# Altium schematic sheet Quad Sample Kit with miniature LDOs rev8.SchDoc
size A
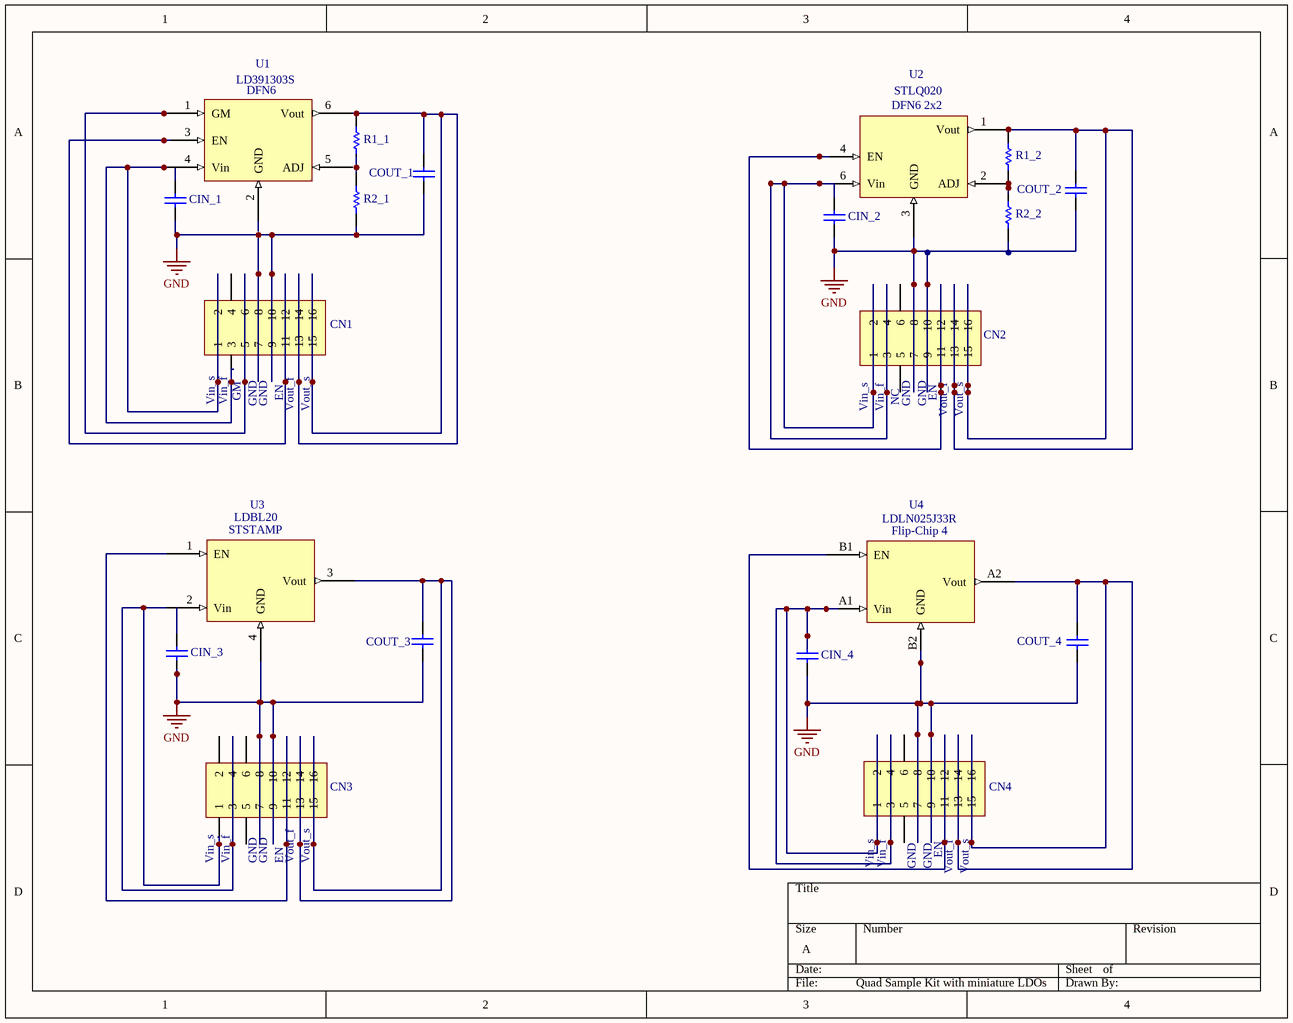
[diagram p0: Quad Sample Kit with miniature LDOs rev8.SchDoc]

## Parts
CIN_1  Cap  [0603]  (value not drawn)
CIN_2  Cap  [0603]  (value not drawn)
CIN_3  Cap  [0603]  (value not drawn)
CIN_4  Cap  [0603]  (value not drawn)
CN1  Header 8X2  [HDR2X8]  (value not drawn)
CN2  Header 8X2  [HDR2X8]  (value not drawn)
CN3  Header 8X2  [HDR2X8]  (value not drawn)
CN4  Header 8X2  [HDR2X8]  (value not drawn)
COUT_1  Cap  [0603]  (value not drawn)
COUT_2  Cap  [0603]  (value not drawn)
COUT_3  Cap  [0603]  (value not drawn)
COUT_4  Cap  [0603]  (value not drawn)
LD391303S  DFN6  [PCBComponent_1]
LDBL20  STSTAMP  [PCBComponent_1]
LDLN025J33R  Flip-Chip 4  [PCBComponent_1]
R1_1  Res1  [0603]  (value not drawn)
R1_2  Res1  [0603]  (value not drawn)
R2_1  Res1  [0603]  (value not drawn)
R2_2  Res1  [0603]  (value not drawn)
STLQ020  DFN6 2x2  [PCBComponent_1]

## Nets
GND: CIN_1.1 CIN_2.1 CIN_3.1 CIN_4.1 CN1.7 CN1.8 CN1.9 CN1.10 CN2.7 CN2.8 CN3.7 CN3.8 CN3.9 CN3.10 CN4.7 CN4.8 CN4.9 CN4.10 COUT_1.1 COUT_2.1 COUT_3.1 COUT_4.1 LDBL20.4(GND) LDLN025J33R.B2(GND) R2_1.1 STLQ020.3(GND)
NetCIN_2_2: CIN_2.2 CN2.1 CN2.2 CN2.3 CN2.4 STLQ020.6(Vin)
NetCIN_4_2: CIN_4.2 CN4.1 CN4.2 CN4.3 CN4.4 LDLN025J33R.A1(Vin)
NetCN1_1: CN1.1 CN1.2 CN1.3 LD391303S.4(Vin)
NetCN1_5: CN1.5 CN1.6 LD391303S.1(GM)
NetCN1_11: CN1.11 CN1.12 LD391303S.3(EN)
NetCN1_13: CN1.13 CN1.14 CN1.15 CN1.16 COUT_1.2 LD391303S.6(Vout) R1_1.2
NetCN2_9: CN2.9 CN2.10
NetCN2_11: CN2.11 CN2.12 STLQ020.4(EN)
NetCN2_13: CN2.13 CN2.14 CN2.15 CN2.16 COUT_2.2 R1_2.2 STLQ020.1(Vout)
NetCN3_1: CN3.1 CN3.3 CN3.4 LDBL20.2(Vin)
NetCN3_11: CN3.11 CN3.12 LDBL20.1(EN)
NetCN3_13: CN3.13 CN3.14 CN3.15 CN3.16 COUT_3.2 LDBL20.3(Vout)
NetCN4_11: CN4.11 CN4.12 LDLN025J33R.B1(EN)
NetCN4_13: CN4.13 CN4.14 CN4.15 CN4.16 COUT_4.2 LDLN025J33R.A2(Vout)
NetR1_1_1: R1_1.1 R2_1.2
NetR1_2_1: R1_2.1 R2_2.2 STLQ020.2(ADJ)

Not connected (* = marked no-connect by the designer): CIN_1 2; CIN_3 2; CN1 4; CN2 5 6; CN3 2 5 6; CN4 5 6; LD391303S 2(GND) 5(ADJ); R2_2 1

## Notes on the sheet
- (near LD391303S) U1
- (near STLQ020) U2
- (near CN1) Vin_s
- (near CN1) Vin_f
- (near CN1) GM
- (near CN1) GND
- (near CN1) EN
- (near CN1) Vout_f
- (near CN1) Vout_s
- (near CN2) Vin_s
- (near CN2) Vin_f
- (near CN2) NC
- (near CN2) GND
- (near CN2) EN
- (near CN2) Vout_f
- (near CN2) Vout_s
- (near LDBL20) U3
- (near LDLN025J33R) Flip-Chip 4
- (near LDLN025J33R) U4
- (near CN3) Vin_s
- (near CN3) Vin_f
- (near CN3) GND
- (near CN3) EN
- (near CN3) Vout_f
- (near CN3) Vout_s
- (near CN4) Vin_s
- (near CN4) Vin_f
- (near CN4) GND
- (near CN4) EN
- (near CN4) Vout_f
- (near CN4) Vout_s

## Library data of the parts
CIN_1-CIN_4 COUT_1-COUT_4 = Cap: Capacitor; Value: 1uF
CN1-CN4 = Header 8X2: Header, 8-Pin, Dual row
LDBL20 LDLN025J33R STLQ020 = Component_1
R1_1 R1_2 R2_1 R2_2 = Res1: Resistor; Value: 1MOhm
